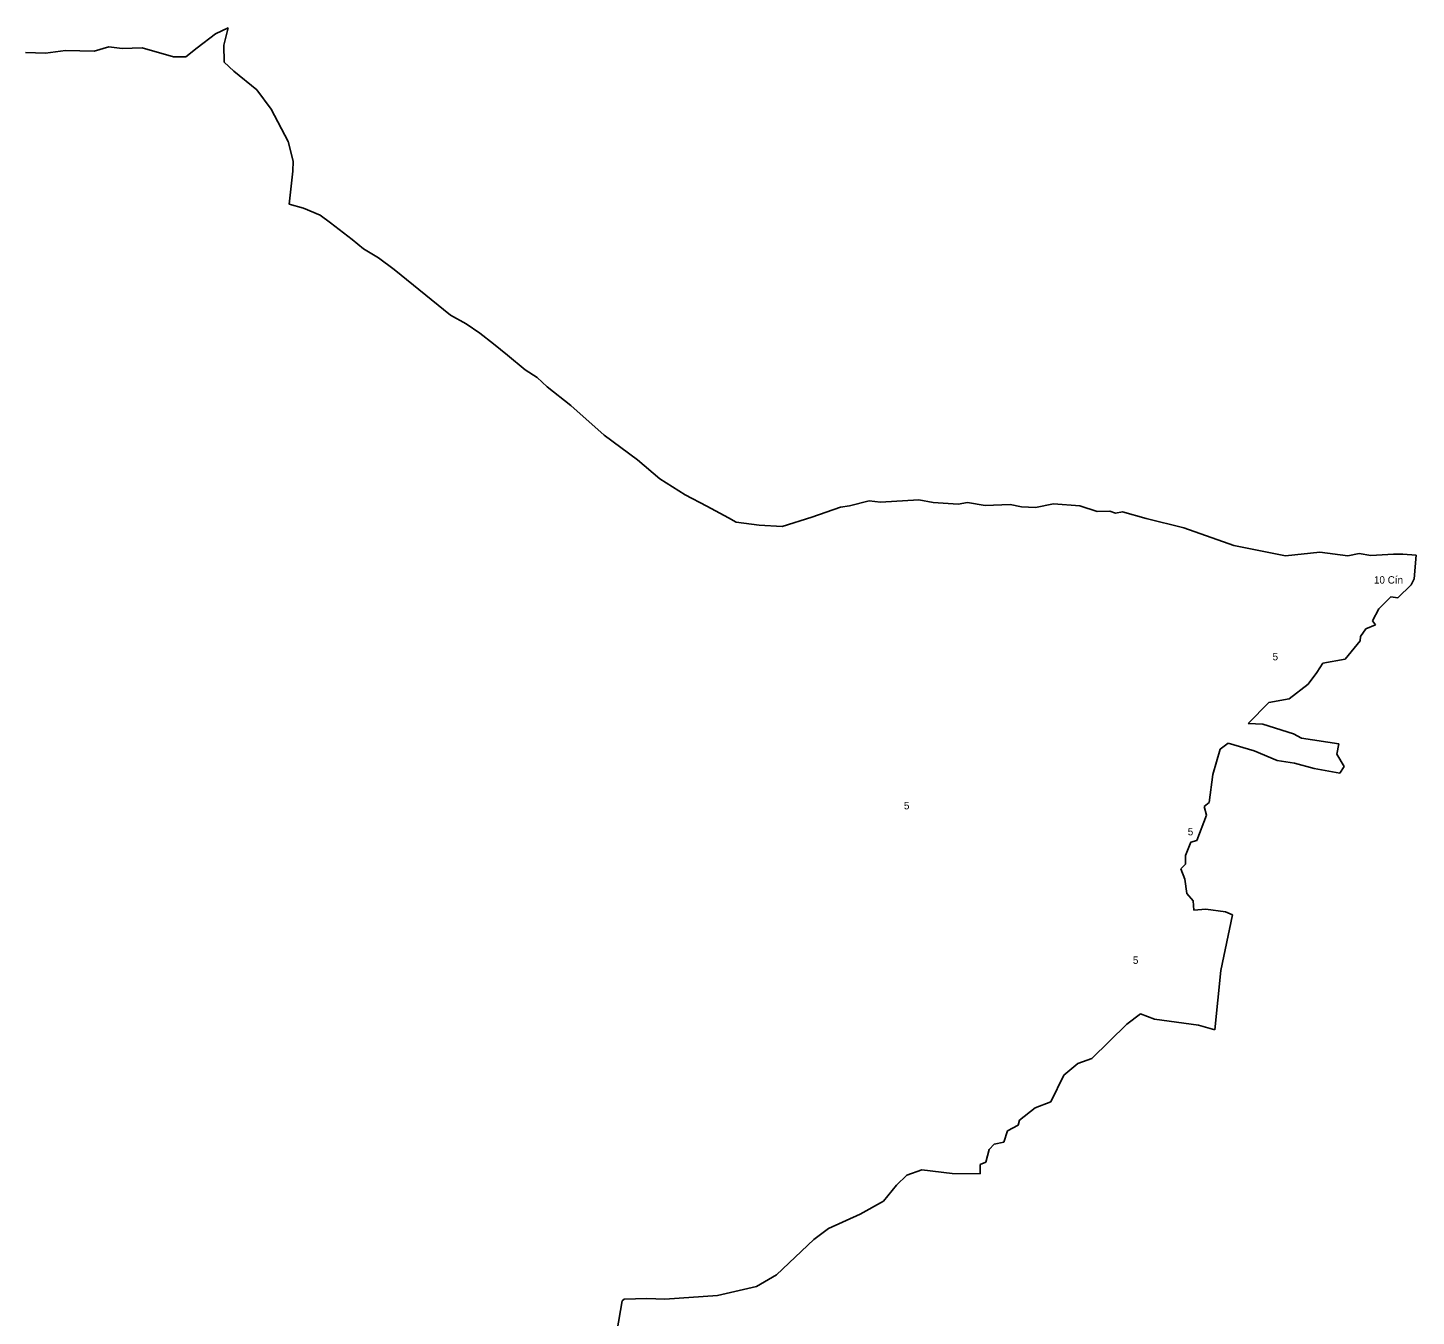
# Model space of a CAD drawing. Extents: x -779790 to -775735, y -971779 to -967735.
# Drawn here: x -777845 to -775735, y -969727 to -967769 of the extents above; entities that cross this region are included whole.
import ezdxf

# ---------------------------------------------------------------- set-up
doc = ezdxf.new("R2010")
doc.units = 0
for name, color, linetype in [('Vrstva 1', 7, 'Continuous'), ('Vrstva 15', 7, 'Continuous'), ('Vrstva 24', 7, 'Continuous')]:
    doc.layers.add(name, color=color, linetype=linetype)

msp = doc.modelspace()

# ---------------------------------------------------------------- linework, layer by layer
at = {"layer": 'Vrstva 1'}
for p, q in [((-776524.32, -969527.59), (-776508.56, -969512.33)), ((-776508.56, -969512.33), (-776485.91, -969504.45)), ((-776485.91, -969504.45), (-776440.11, -969509.86)), ((-776440.11, -969509.86), (-776397.27, -969510.36)), ((-776544.01, -969551.72), (-776524.32, -969527.59)), ((-776579.47, -969571.91), (-776544.01, -969551.72)), ((-776627.85, -969593.7), (-776579.47, -969571.91)), ((-776650.25, -969609.95), (-776627.85, -969593.7)), ((-776706.63, -969663.62), (-776650.25, -969609.95)), ((-776706.63, -969663.62), (-776737.16, -969681.72)), ((-776737.16, -969681.72), (-776796.74, -969695.02)), ((-776941.52, -969703.14), (-776949.64, -969750.41)), ((-776938.32, -969700.92), (-776941.52, -969703.14)), ((-776904.09, -969699.94), (-776938.32, -969700.92)), ((-776876.52, -969700.92), (-776904.09, -969699.94)), ((-776796.74, -969695.02), (-776876.52, -969700.92))]:
    msp.add_line(p, q, dxfattribs=at)
at = {"layer": 'Vrstva 15'}
for p, q in [((-777559.28, -967778.08), (-777539.91, -967768.79)), ((-777539.91, -967768.79), (-777546.77, -967795.03)), ((-777587.14, -967799.07), (-777559.28, -967778.08)), ((-777848.31, -967806.34), (-777817.63, -967807.55)), ((-777817.63, -967807.55), (-777787.35, -967803.11)), ((-777787.35, -967803.11), (-777743.76, -967804.32)), ((-777743.76, -967804.32), (-777721.55, -967797.86)), ((-777721.55, -967797.86), (-777700.97, -967800.28)), ((-777700.97, -967800.28), (-777670.7, -967799.07)), ((-777670.7, -967799.07), (-777623.06, -967812.79)), ((-777623.06, -967812.79), (-777604.49, -967812.79)), ((-777604.49, -967812.79), (-777587.14, -967799.07)), ((-777546.77, -967795.03), (-777546.36, -967821.27)), ((-777546.36, -967821.27), (-777531.43, -967834.99)), ((-777531.43, -967834.99), (-777496.71, -967863.25)), ((-777496.71, -967863.25), (-777474.92, -967892.72)), ((-777474.92, -967892.72), (-777449.09, -967941.66)), ((-777449.09, -967941.66), (-777441.22, -967971.33)), ((-777441.22, -967971.33), (-777441.82, -967986.58)), ((-777447.47, -968036.64), (-777441.82, -967986.58)), ((-777425.67, -968042.69), (-777447.47, -968036.64)), ((-777400.24, -968053.59), (-777425.67, -968042.69)), ((-777384.5, -968065.3), (-777400.24, -968053.59)), ((-777351.8, -968090.73), (-777384.5, -968065.3)), ((-777334.44, -968104.86), (-777351.8, -968090.73)), ((-777311.84, -968118.39), (-777334.44, -968104.86)), ((-777287.62, -968136.15), (-777311.84, -968118.39)), ((-777202.04, -968205.59), (-777287.62, -968136.15)), ((-777178.63, -968218.5), (-777202.04, -968205.59)), ((-777157.64, -968233.04), (-777178.63, -968218.5)), ((-777136.65, -968249.18), (-777157.64, -968233.04)), ((-777115.66, -968266.14), (-777136.65, -968249.18)), ((-777089.01, -968288.74), (-777115.66, -968266.14)), ((-777070.45, -968300.04), (-777089.01, -968288.74)), ((-777055.11, -968314.58), (-777070.45, -968300.04)), ((-777019.58, -968342.83), (-777055.11, -968314.58)), ((-776968.72, -968388.05), (-777019.58, -968342.83)), ((-776917.86, -968425.18), (-776968.72, -968388.05)), ((-776883.95, -968454.25), (-776917.86, -968425.18)), ((-776845.6, -968478.67), (-776883.95, -968454.25)), ((-776812.9, -968495.62), (-776845.6, -968478.67)), ((-776565.85, -968487.54), (-776595.73, -968495.21)), ((-776548.9, -968489.56), (-776565.85, -968487.54)), ((-776490.77, -968486.33), (-776548.9, -968489.56)), ((-776468.57, -968490.37), (-776490.77, -968486.33)), ((-776430.63, -968492.79), (-776468.57, -968490.37)), ((-776416.5, -968490.37), (-776430.63, -968492.79)), ((-776389.86, -968494.81), (-776416.5, -968490.37)), ((-776779.8, -968513.38), (-776812.9, -968495.62)), ((-776609.45, -968497.23), (-776653.05, -968512.57)), ((-776595.73, -968495.21), (-776609.45, -968497.23)), ((-776351.51, -968493.19), (-776389.86, -968494.81)), ((-776334.56, -968496.83), (-776351.51, -968493.19)), ((-776313.16, -968498.04), (-776334.56, -968496.83)), ((-776285.71, -968492.39), (-776313.16, -968498.04)), ((-776245.75, -968495.21), (-776285.71, -968492.39)), ((-776219.51, -968504.09), (-776245.75, -968495.21)), ((-776200.54, -968503.28), (-776219.51, -968504.09)), ((-776191.66, -968506.51), (-776200.54, -968503.28)), ((-776181.16, -968504.49), (-776191.66, -968506.51)), ((-776145.24, -968514.59), (-776181.16, -968504.49)), ((-776768.1, -968520.24), (-776779.8, -968513.38)), ((-776732.98, -968524.68), (-776768.1, -968520.24)), ((-776698.26, -968526.7), (-776732.98, -968524.68)), ((-776653.05, -968512.57), (-776698.26, -968526.7)), ((-776087.92, -968528.71), (-776145.24, -968514.59)), ((-776011.62, -968555.36), (-776087.92, -968528.71)), ((-775933.31, -968571.5), (-776011.62, -968555.36)), ((-775881.24, -968565.85), (-775933.31, -968571.5)), ((-775838.45, -968571.1), (-775881.24, -968565.85)), ((-775821.49, -968567.46), (-775838.45, -968571.1)), ((-775803.73, -968570.69), (-775821.49, -968567.46)), ((-775769.02, -968568.67), (-775803.73, -968570.69)), ((-775755.29, -968568.67), (-775769.02, -968568.67)), ((-775755.29, -968568.67), (-775734.7, -968570.29)), ((-775734.7, -968570.29), (-775737.93, -968606.21)), ((-775742.37, -968615.5), (-775762.55, -968635.28)), ((-775737.93, -968606.21), (-775742.37, -968615.5)), ((-775791.62, -968651.83), (-775773.46, -968633.67)), ((-775773.46, -968633.67), (-775762.55, -968635.28)), ((-775800.91, -968670), (-775791.62, -968651.83)), ((-775811.4, -968682.11), (-775796.47, -968676.05)), ((-775796.47, -968676.05), (-775800.91, -968670)), ((-775842.89, -968728.12), (-775819.88, -968700.67)), ((-775819.88, -968700.67), (-775819.47, -968693.81)), ((-775819.47, -968693.81), (-775811.4, -968682.11)), ((-775885.68, -968748.31), (-775876.8, -968734.18)), ((-775876.8, -968734.18), (-775842.89, -968728.12)), ((-775899, -968766.06), (-775885.68, -968748.31)), ((-775927.66, -968788.67), (-775899, -968766.06)), ((-775990.23, -968825.81), (-775958.75, -968793.92)), ((-775958.75, -968793.92), (-775927.66, -968788.67)), ((-775967.63, -968827.02), (-775990.23, -968825.81)), ((-775921.2, -968841.55), (-775967.63, -968827.02)), ((-775909.09, -968848.41), (-775921.2, -968841.55)), ((-775852.18, -968856.89), (-775909.09, -968848.41)), ((-776043.92, -968903.72), (-776032.62, -968864.96)), ((-776032.62, -968864.96), (-776020.51, -968855.68)), ((-776020.51, -968855.68), (-775980.95, -968867.39)), ((-775980.95, -968867.39), (-775945.83, -968882.32)), ((-775855.41, -968872.63), (-775852.18, -968856.89)), ((-775945.83, -968882.32), (-775919.59, -968886.36)), ((-775919.59, -968886.36), (-775889.72, -968894.43)), ((-775844.1, -968891.2), (-775855.41, -968872.63)), ((-775850.97, -968901.29), (-775844.1, -968891.2)), ((-776049.17, -968946.1), (-776043.92, -968903.72)), ((-775889.72, -968894.43), (-775850.97, -968901.29)), ((-776056.84, -968952.16), (-776049.17, -968946.1)), ((-776053.2, -968965.48), (-776056.84, -968952.16)), ((-776068.14, -969003.83), (-776053.2, -968965.48)), ((-776085.5, -969026.43), (-776077.42, -969006.25)), ((-776077.42, -969006.25), (-776068.14, -969003.83)), ((-776085.09, -969039.75), (-776085.5, -969026.43)), ((-776092.37, -969047.03), (-776085.09, -969039.75)), ((-776086.31, -969062.77), (-776092.37, -969047.03)), ((-776083.49, -969084.16), (-776086.31, -969062.77)), ((-776073.8, -969095.47), (-776083.49, -969084.16)), ((-776072.59, -969109.6), (-776073.8, -969095.47)), ((-776054.42, -969107.98), (-776072.59, -969109.6)), ((-776024.55, -969112.42), (-776054.42, -969107.98)), ((-776031.41, -969201.63), (-776014.05, -969116.86)), ((-776014.05, -969116.86), (-776024.55, -969112.42)), ((-776040.7, -969291.66), (-776031.41, -969201.63)), ((-776174.31, -969282.77), (-776153.72, -969267.43)), ((-776153.72, -969267.43), (-776132.33, -969275.51)), ((-776227.59, -969335.25), (-776174.31, -969282.77)), ((-776132.33, -969275.51), (-776065.72, -969284.39)), ((-776065.72, -969284.39), (-776040.7, -969291.66)), ((-776269.98, -969360.68), (-776248.99, -969342.92)), ((-776248.99, -969342.92), (-776227.59, -969335.25)), ((-776289.76, -969401.05), (-776269.98, -969360.68)), ((-776337.39, -969428.6), (-776313.58, -969410.04)), ((-776313.58, -969410.04), (-776289.76, -969401.05)), ((-776355.76, -969444.95), (-776339.61, -969436.48)), ((-776339.61, -969436.48), (-776337.39, -969428.6)), ((-776361.21, -969462.11), (-776355.76, -969444.95)), ((-776388.86, -969492.59), (-776383.82, -969473.41)), ((-776383.82, -969473.41), (-776375.94, -969465.14)), ((-776375.94, -969465.14), (-776361.21, -969462.11)), ((-776397.34, -969496.02), (-776388.86, -969492.59)), ((-776397.27, -969510.36), (-776397.34, -969496.02))]:
    msp.add_line(p, q, dxfattribs=at)

# ---------------------------------------------------------------- texts
at = {"layer": 'Vrstva 24'}
for s, p in [('10 Cín ', (-775798.987, -968613.463)), ('5', (-775953.023, -968730.033)), ('5', (-776513.253, -968956.453)), ('5', (-776081.883, -968995.963)), ('5', (-776165.293, -969191.333))]:
    msp.add_text(s, height=11.25, dxfattribs=at).set_placement(p)

doc.saveas('drawing.dxf')
